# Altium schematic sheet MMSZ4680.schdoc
size 127 x 101 mm
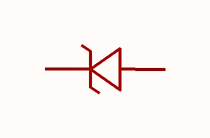
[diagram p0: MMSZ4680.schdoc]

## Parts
U?  mmsz4680  [SOD-123_L2.7-W1.6-LS3.7-RD-1]  (value not drawn)

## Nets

Not connected (* = marked no-connect by the designer): U? 1(C) 2(A)

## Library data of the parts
U? = mmsz4680: 二极管配置:独立式;稳压值(标称值):2.2V;稳压值(范围):2.09V~2.31V;功率(Pd):500mW;; Manufacturer: CJ(江苏长电/长晶); AddInBom: yes; ModelId: 528459655f7d4601a76356f3191c812b; ModelTransform: 151.575,66.929,0,0,0,0,0,0,0; Diode Configuration: 独立式; Zener Voltage (Nom): 2.2V; Reverse Leakage Current (Ir): 4uA@1V; Power Dissipation: 500mW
